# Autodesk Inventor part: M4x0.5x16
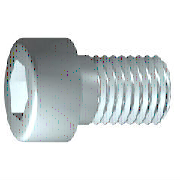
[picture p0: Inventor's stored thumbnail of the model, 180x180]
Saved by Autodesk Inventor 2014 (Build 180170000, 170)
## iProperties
IsCustomPart: 1
Company: 한국ATC센터
Created: 2009-02
Part Number: M4x0.5x16
Material: 강, 연강
Description: 6각머리 태핑 나사
Document SubType Name: Modeling
Standard: KS B 1003
Designer: KYOUNG IL JANG
Standards Organization: KS
Language: ko-KR
Size Designation: M 4 x 16
Categories: <MemberInstance><Categories><Category DisplayName="조임쇠" InternalName="e4da775c-781d-43d5-af7c-5136215cf5a6" Mnemonic="FSTN"><Category DisplayName="볼트" InternalN
Density: 7.86 g/cm^3
Mass: 2.62973 g
Surface Area: 3.81118 cm^2
Volume: 0.334572 cm^3
Vendor: CBT Solutions
Appearance: 연마 - 진회색
Author: KYOUNG IL JANG
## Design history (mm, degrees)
sketch "스케치1"
  geometry: L1 (-1, 0)-(16, 0); L2 (16, 0)-(16, 2); L3 (16, 2)-(1.75, 2); L4 (1.75, 2)-(1.32, 2); L5 (1.32, 2)-(0, 2); L6 (0, 2)-(0, 3.5); L7 (0, 3.5)-(-4, 3.5); L8 (-4, 3.5)-(-4, 1.732); L9 (-4, 1.732)-(-2, 1.732); L10 (-2, 1.732)-(-1, 0); L11 (-8, 0)-(20, 0) reference; L12 (0, -0.7)-(0, 4.2) reference; L13 (1.75, 2)-(0, 2)
  constraints: 22 end point, 6 parallel, 2 collinear, 2 perpendicular, 1 horizontal, 1 point on line
  dimensions: "d1" = 14.25 distance from line of L3.end L2 (= GEL); "d2" = 0.42952 distance of L4.end L3.end (computed from GAL); "d3" = 4 distance between parallel lines of L8 L6 (= KOH); "d4" = 2 distance of L8.end L9.end (= INTI); "d5" = 60 deg angle of L10 L1; "d6" = 4 diameter of L3 L1 (= GD); "d7" = 4 diameter of L5 L1 (= BDM); "d8" = 3.4641 diameter of L9 L1 (= 1.1547 x SW); "d9" = 7 diameter of L7 L1 (= KOD); "d26" = 16 distance between parallel lines of L12 L2 (= NLG)
revolve "본체" sketch "스케치1" stored, may be unused: angle "d10" = 90 deg
sketch "스케치2"
  geometry: L1 (0, -4.9)-(0, 4.9) reference; L2 (-4.9, 0)-(4.9, 0) reference; L3 (1.732, 0)-(0.866, -1.5); L4 (0.866, -1.5)-(-0.866, -1.5); L5 (-0.866, -1.5)-(-1.732, 0); L6 (-1.732, 0)-(-0.866, 1.5); L7 (-0.866, 1.5)-(0.866, 1.5); L8 (0.866, 1.5)-(1.732, 0); 2 further points
  constraints: 12 end point, 1 coincident, 1 horizontal alignment, 1 point on line, 12 other
extrude "슬롯" join sketch "스케치2" stored distance "d11" = 10; taper "d12" = 0 deg
workplane "Work Plane1"
fillet "Fillet2" dims "d30" = 0.1 (= R)
body "Solid1"
fillet "모깎기1" dims "d17" = 0.4 (= RR)
feature "스레드" dims "d13" = 14.25 (= GEL), "d14" = 0
chamfer "모따기1" distance "d15" = 0.42941 (= -0.5 x SPD + 0.5 x GD); stored, may be unused: second distance "d16" = 0.42941 (= GUL), angle "d27" = 45 deg
other parameters: "GD" = 4 (= NND) [user parameter; used in 2 equation terms], "NLG" = 16 [user parameter; used in 1 equation term], "GEL" = 14.25 [user parameter; used in 2 equation terms], "KOD" = 7 [user parameter; used in 1 equation term], "KOH" = 4 [user parameter; used in 1 equation term], "INTI" = 2 [user parameter; used in 1 equation term], "GAL" = 0.42941 (= 0.61345 x PTC) [user parameter; used in 1 equation term], "GUL" = 0.42941 (= 0.61345 x PTC) [user parameter; used in 1 equation term], "BDM" = 4 (= NND) [user parameter; used in 1 equation term], "SW" = 3 [user parameter; used in 2 equation terms], "RR" = 0.4 [user parameter; used in 1 equation term], "SPD" = 3.14117 (= NND - 1.2269 x PTC) [user parameter; used in 1 equation term], "d19" = 0, "d28" = 0, "d29" = 0, "R" = 0.1 [user parameter; used in 1 equation term], "PHH" = 0.2 [user parameter], "GD1" = 3.14117 (= THREADDIA - 1.2269 x PTC) [user parameter], "THREADDIA" = 4 [user parameter; used in 1 equation term], "FAWI" = 45 deg [user parameter], "TPU" = 14.28571 (computed from PTC) [user parameter], "PTC" = 0.7 [user parameter; used in 5 equation terms], "NND" = 4 [user parameter; used in 3 equation terms], "TOA" = 30 deg [user parameter], "E0" = 3.465 (= 1.155 x SW) [user parameter]
